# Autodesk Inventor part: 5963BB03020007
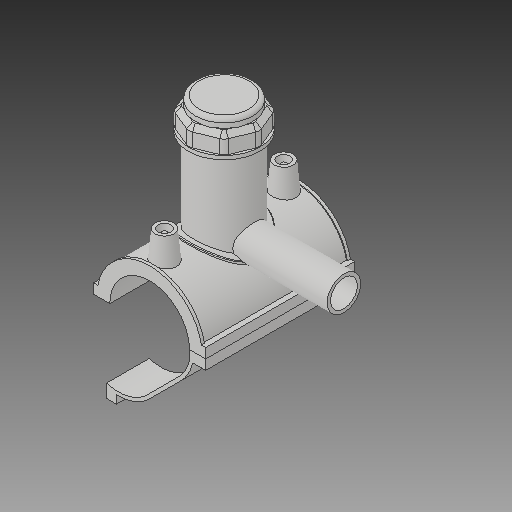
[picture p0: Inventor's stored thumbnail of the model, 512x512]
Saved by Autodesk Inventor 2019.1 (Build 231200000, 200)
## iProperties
Created: 2017-07
Part Number: 5963BB03020007
Material: Generic
Description: PLASSON TAPPING SADDLE 2''IPS x 1 3/4''IPS
Document SubType Name: Modeling
Designer: KIM
Mass: 1712.7 g
Surface Area: 2671.49 cm^2
Volume: 1712.7 cm^3
Density: 1 g/cm^3
Appearance: Default
Author: KIM
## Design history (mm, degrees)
derived "5963B.ipt"
feature "Solid1::5963B.ipt"
feature "Solid2::5963B.ipt"
feature "Solid4::5963B.ipt"
feature "Solid5::5963B.ipt"
tag "TaggingFeature1"
body "Solid1"
body "Solid2"
other parameters: "d0" = 63.1, "d2" = 88.9, "d3" = 15.775, "d4" = 118.11, "d5" = 0, "d6" = 0.1, "d8" = 0, "d19" = 6, "d20" = 6, "d21" = 70.866, "d23" = 0, "d24" = 35.433, "d26" = 0, "d29" = 3, "d30" = 21.03333, "d31" = 6, "d32" = 0, "d33" = 0, "d34" = 0.6, "d40" = 42.6556, "d41" = 56.79, "d43" = 0, "d45" = 0, "d47" = 111.881, "d70" = 15, "d72" = 0, "d73" = 6, "d75" = 5, "d76" = 0, "d77" = 3.155, "d78" = 61.55, "d79" = 15, "d80" = 47.244, "d82" = 5 deg, "d84" = 4, "d85" = 14, "d86" = 0, "d87" = 3, "d88" = 0, "d89" = 1, "d90" = 1, "d91" = 94.488, "d92" = 0, "d93" = 0.5, "d94" = 33.21053, "d96" = 83.6706, "d97" = 2.3622, "d98" = 0, "d102" = 0.631, "d120" = 140 deg, "d121" = 24.228, "d122" = 20 deg, "d123" = 164.06, "d124" = 49.218, "d126" = 0, "d143" = 64.993, "d145" = 14.56154, "d149" = 0.9465, "d150" = 16.01769, "d153" = 118.11, "d154" = 0, "d156" = 41.015, "d157" = 160 deg, "d159" = 3.786, "d161" = 0.9465, "d162" = 70.866, "d163" = 0, "d164" = 31.55, "d167" = 6.31, "d168" = 40.01463, "d170" = 3.2805, "d172" = 0, "d173" = 1, "d175" = 31.55, "d176" = 20 deg, "d177" = 4.417, "d178" = 18.93, "d180" = 0, "d183" = 7.572, "d184" = 3.5336, "d185" = 38.38575, "d186" = 38.38575, "d187" = 41.015, "d188" = 5.679, "d189" = 4.417, "d190" = 0, "d191" = 61.5225, "d193" = 6.1236, "d194" = 4.13385, "d195" = 90 deg, "d197" = 0, "d199" = 0, "d200" = 9.465, "d202" = 0, "d203" = 98.044, "d204" = 53.9505, "d205" = 39.753, "d206" = 48.2715, "d207" = 73.533, "d208" = 76.47432, "d209" = 91.18092, "d210" = 48.8394, "d211" = 56.79, "d212" = 45.432, "d213" = -3.5118, "d216" = 0, "d217" = 6.31, "d218" = 3.155, "d219" = 0.631, "d222" = 63.1, "d224" = 0, "d230" = 3.786, "d233" = 6, "d236" = 44.45, "d237" = 35.433, "d238" = 6.02433, "d240" = 35.433, "d241" = 35.433, "d242" = 35.433, "d243" = 6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
